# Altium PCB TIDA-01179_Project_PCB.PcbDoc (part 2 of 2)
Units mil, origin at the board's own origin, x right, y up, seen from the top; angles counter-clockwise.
Board outline 3149.61 x 2755.91 mil, 4 copper layers (Top Layer, 2nd Layer, 3rd layer, Bottom Layer), stack 51.6 mil thick; 141 components, 52 nets, 310 pads, 228 vias.
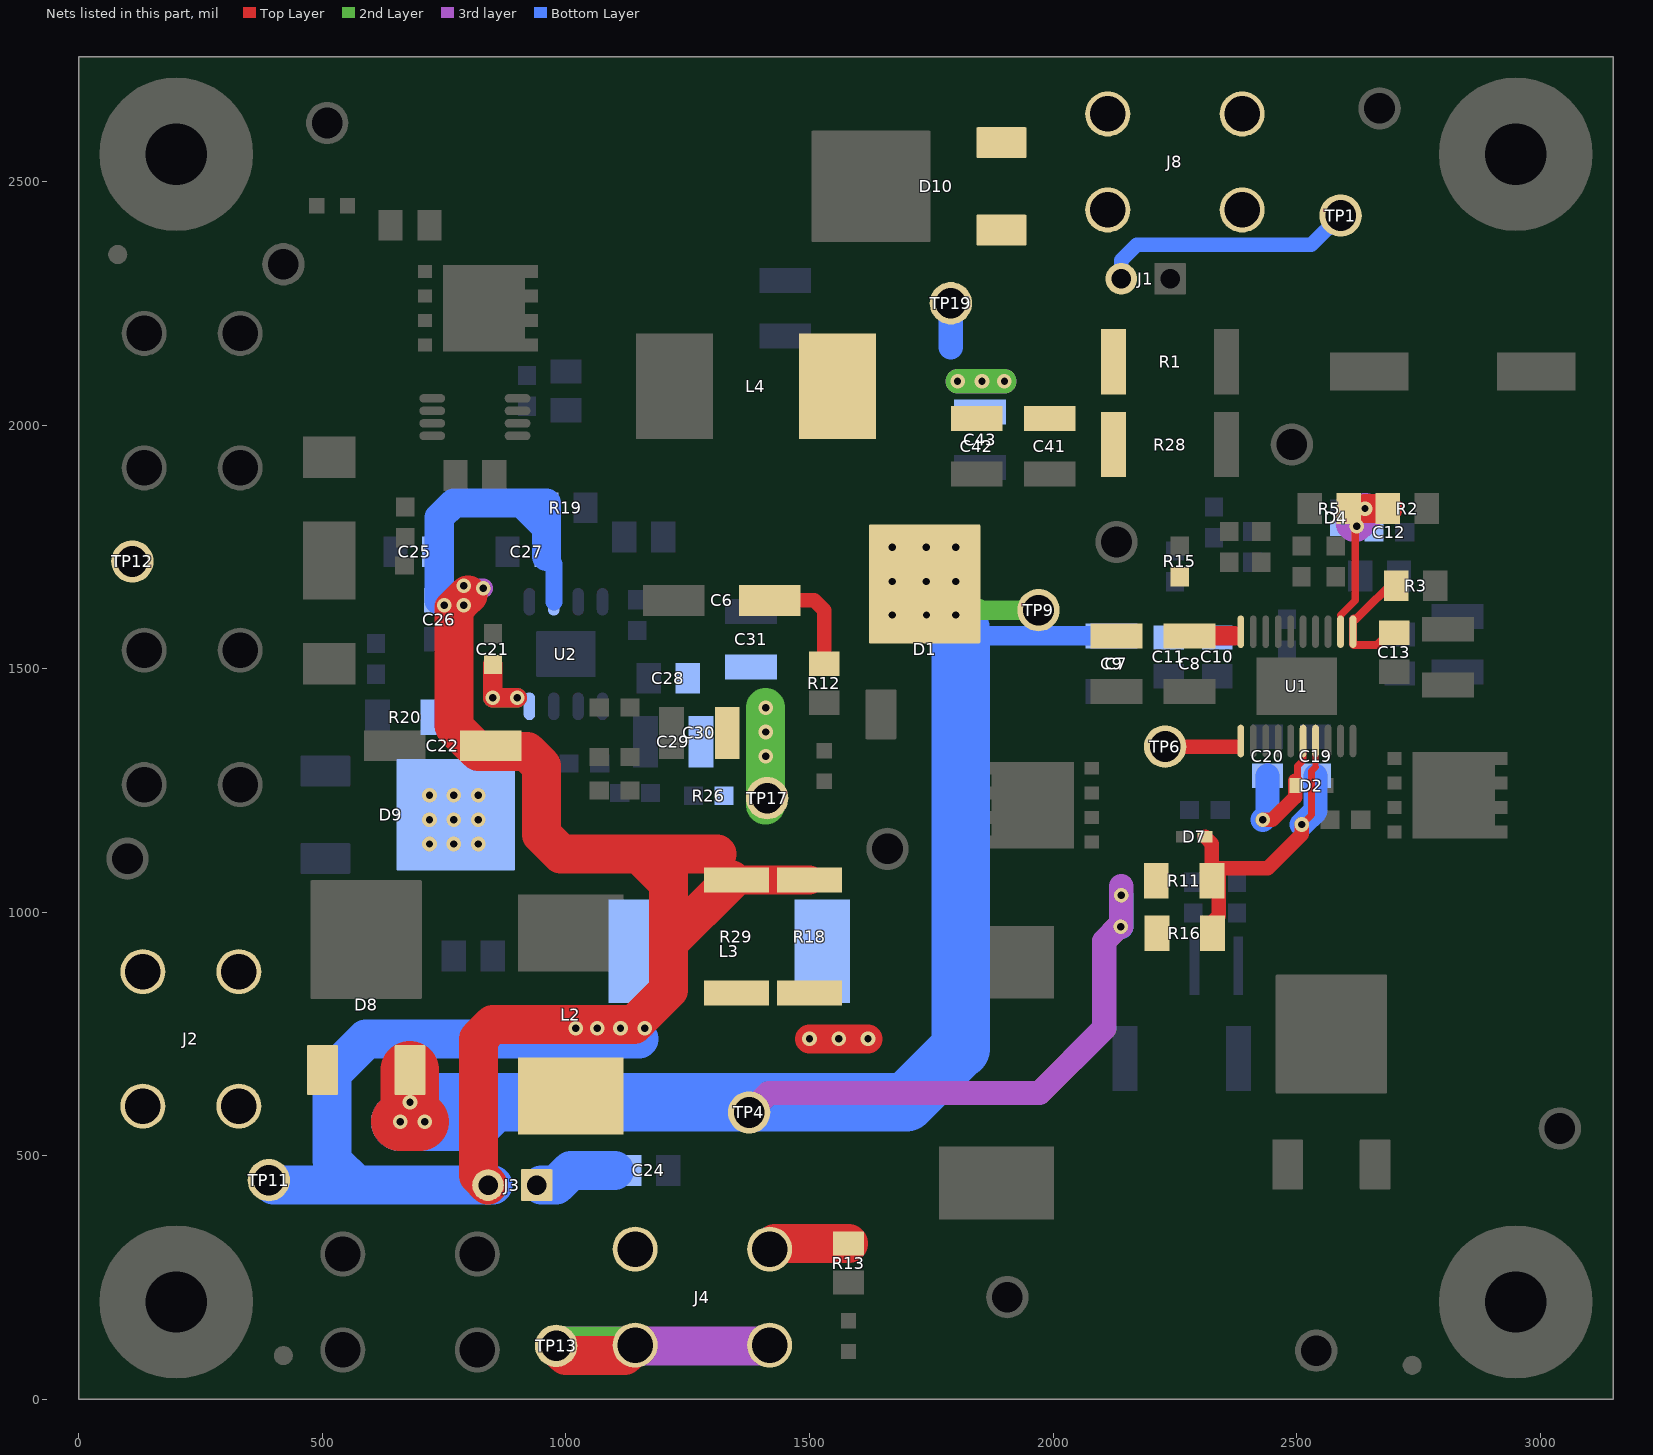
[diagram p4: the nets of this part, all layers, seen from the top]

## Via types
v1: diameter 30, hole 15, Top Layer to Bottom Layer, 210 vias
v2: diameter 19.68, hole 7.87, Top Layer to Bottom Layer, 12 vias
v3: diameter 19.68, hole 7.87, Top Layer to Bottom Layer, tented top, 6 vias

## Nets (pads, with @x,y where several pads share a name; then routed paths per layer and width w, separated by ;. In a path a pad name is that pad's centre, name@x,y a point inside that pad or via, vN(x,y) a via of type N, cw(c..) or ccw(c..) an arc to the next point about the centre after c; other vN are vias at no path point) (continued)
SW_540: C21.1 D9.4 L3.1 R20.2 TP12.1 U2.8 | length 168.5
  Top Layer w40: C21.1@850,1508.5 v1(850,1440) v1(900,1440)
  2nd Layer w40: v1(850,1440) v1(900,1440)
  other v1: 720,1140 770,1140 820,1140 720,1190 770,1190 820,1190 720,1240 770,1240 820,1240
SYNC_5118: TP6.1 U1.11 | length 147
  Top Layer w30: TP6.1@2230,1340 2377,1340
UVLO_5118: C12.1 D4.1 R2.1 R5.2 U1.2 | length 369.8
  Top Layer w13: U1.2@2589.8,1575.91 2589.8,1609.8
  Top Layer w15: 2589.8,1609.8 2620,1640 R5.2@2620,1800
  Top Layer w60: v1(2640,1828.54) R2.1@2686.61,1828.54
  3rd layer w80: v1@2620,1800 v1@2640,1820
  Bottom Layer w30: v1@2620,1800 v1@2640,1820 ; C12.1@2640,1798.5 v1@2640,1820 ; v1(2640,1828.54) v1@2640,1820
  other v1: 2623,1792
V_HVBAT_+12V: D10.1 D10.3 J8.1 J8.2 J8.3 J8.4
V_HVBAT_+15V: D8.1 J2.1 J2.2 J2.3 J2.4
VBAT_FILT: C41.1 C42.1 C43.1 J1.2 L4.2 R1.1 R28.1 TP1.1 TP19.1 | length 808.4
  3rd layer w50: v1(1803.86,2090) v1(1853.86,2090) v1(1900,2090)
  2nd Layer w50: v1(1803.86,2090) v1(1853.86,2090) v1(1900,2090)
  Bottom Layer w30: J1.2@2140,2300 2140,2338 2172,2370 2530,2370 TP1.1@2590,2430
  Bottom Layer w50: 1790,2160 TP19.1@1790,2250
VCC_5118: C20.1 D2.2 U1.16 | length 301.7
  Top Layer w13: 2513.03,1311.57 U1.16@2513.03,1351.5
  Top Layer w14: D2.2@2496.54,1270 2501.46,1274.92 2501.46,1300 2513.03,1311.57
  Top Layer w30: v1(2430,1190) 2450,1190 2496.54,1236.54 D2.2@2496.54,1270
  Bottom Layer w50: v1(2430,1190) 2440,1200 C20.1@2440,1280
VCCX_5118: C19.1 D7.1 R11.1 R16.1 U1.17 | length 739.6
  Top Layer w13: 2538.62,1298.31 U1.17@2538.62,1351.5
  Top Layer w14: v1(2510,1180) 2530,1200 2530,1289.68 2538.62,1298.31
  Top Layer w30: D7.1@2311.65,1154.57 2325.79,1140.43 R11.1@2325.79,1090 ; R11.1@2325.79,1064.57 R11.1@2325.79,1090 ; R16.1@2327.09,980 2340,992.91 R11.1@2340,1090 ; v1(2510,1180) 2510,1160 2440,1090 R11.1@2325.79,1090
  Bottom Layer w50: v1(2510,1180) 2538.62,1208.62 C19.1@2538.62,1280
VFILT_+15V: C24.1 J3.1 L2.2 R18.1 R29.1 | length 162.4
  Bottom Layer w80: J3.1@950,440 980,440 1010,470 1100,470
VIN_540: C22.1 C25.1 C26.1 C27.1 J3.2 R18.2 R19.2 R29.2 TP11.1 U2.2 | length 4816.6
  Top Layer w60: R29.2@1340,1066.14 R18.2@1500,1066.14
  Top Layer w80: 798.68,1651.62 770,1622.94 770,1383.16 772.07,1383.16 772.07,1377.93 820,1330 920,1330 950,1300 950,1160 990,1120 1150,1120 ; J3.2@840,440 820,460 820,740 850,770 1140,770 1210,840 1210,936.14 ; 1310,1120 1210,1120 ; R29.2@1340,1066.14 1210,936.14 ; 1150,1120 1210,1120 ; 1150,1120 1210,1060 ; 1210,936.14 1210,1060 ; 1210,1060 1210,1120
  3rd layer w40: v1@820,1660 v1(790,1630) v1(750,1630) 785.3,1665.3 v1(830,1665.3) ; v1(1020,762) v1(1064,762) v1(1112,762) v1(1162,762)
  Bottom Layer w35: U2.2@975,1637.28 C27.1@975,1715
  Bottom Layer w60: C26.1@740,1640 740,1810 770,1840 910,1840 ; C27.1@960,1730 960,1790 ; 910,1840 960,1840 960,1790 ; 910,1840 960,1790
  Bottom Layer w80: TP11.1@390,450 400,440 570,440 ; J3.2@850,440 J3.2@840,440 570,440 ; 1150,740 590,740 520,670 520,490 570,440
  other v1: 790,1670
VIN_5118: C13.1 R3.1 U1.1 | length 239.8
  Top Layer w17: R3.1@2690,1670 2640,1620 2622.48,1602.48 2616.92,1602.48 2615.39,1600.95 U1.1@2615.39,1575.91 2615.39,1550.14 2616.84,1548.69 2665.23,1548.69 C13.1@2690.24,1573.7
VOUT_+5V: C28.1 C29.1 C30.1 C31.1 J4.1 J4.2 J4.3 J4.4 L3.2 R13.2 R26.2 TP13.1 TP17.1 | length 1391.4
  Top Layer w60: v1(1500,740) v1(1560,740) v1(1620,740)
  Top Layer w80: TP13.1@980,110 1000,90 1120.5,90 J4.1@1142,111.5 ; J4.4@1418,308.5 1429.5,320 R13.2@1580,320
  3rd layer w40: v1(1500,740) v1(1560,740) v1(1620,740)
  3rd layer w80: TP13.1@980,110 1416.5,110 J4.3@1418,111.5 ; TP17.1@1410,1237 TP17.1@1413,1234
  2nd Layer w80: TP13.1@980,110 1140.5,110 J4.1@1142,111.5 ; TP17.1@1410,1220 v1(1410,1320) v1(1410,1370) v1(1410,1420)
VOUT_+15V: C6.1 C7.1 C8.1 C9.1 C10.1 C11.1 D1.4 D8.3 R11.2 R12.2 R15.2 R16.2 TP4.1 TP9.1 U1.10 | length 4381.8
  Top Layer w30: C6.1@1418.43,1640 1510,1640 1530,1620 R12.2@1530,1500
  Top Layer w40: C8.1@2280,1567.09 2372,1567.09
  Top Layer w120: v1(660,570) v1@700,570 ; 679.76,580.24 D8.3@679.76,676.14
  3rd layer w50: TP4.1@1376,589 1416,629 1972,629 2104.6,761.6 2104.6,940.92 2133.68,970 v1(2139,970) 2140,971 v1(2140,1034.57) 2140,1053
  2nd Layer w40: 1848,1623 1851,1620 TP9.1@1970,1620
  Bottom Layer w20: 1698,610 1718,590
  Bottom Layer w40: 1810,1567.09 C9.1@2120,1567.09
  Bottom Layer w50: v1@2140,970 v1(2140,1034.57)
  Bottom Layer w120: 1810,1580 1810,1567.09 1810,720 1808,720 1698,610 850,610 ; 850,610 700,610 v1(660,570) v1(710,570) 810,570 850,610
  other v1: 680,610 1670,1610 1740,1610 1800,1610 1670,1678.98 1739.61,1678.98 1800,1678.98 1670,1748.98 1739.61,1748.98 1800,1748.98
pads on no net: FID1.1 FID2.1 FID3.1 H1.1 H2.1 H3.1 H4.1 H5.0 H6.0 H7.0 H8.0

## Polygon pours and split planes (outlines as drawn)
GND on Top Layer "TOP_LAYER_GND_P298" (solid, remove dead copper, pour order 298): 0,0 3149.61,0 3149.61,2755.91 0,2755.91 0,0
VOUT_+5V on Top Layer "TOP_LAYER_VOUT_+5V_P270" (solid, remove dead copper, pour order 270): 1120,380 980,380 950,350 950,120 950,80 990,40 1490,40 1530,80 1530,332.48 1528.5,333.98 1528.5,341.5 1490,380 980,380
CATHODE on Top Layer "TOP_LAYER_CATHODE_P230" (solid, remove dead copper, pour order 230): 1430,1800 1430,2264.61 1750,2264.61 1750,2755.91 770,2755.91 765.91,2760 10,2760 0,2750 0,2120 20,2100 1060,2100 1100,2060 1100,1858.7 1158.7,1800
SW_540 on Top Layer "TOP_LAYER_SW_540_P248" (solid, remove dead copper, pour order 248): 660,1270 640,1250 640,1170 700.57,1109.43 702.35,1109.43 849.43,1109.43 880,1140 880,1250 860,1270
NetC23_1 on Top Layer "TOP_LAYER_NETC23_1_P251" (solid, remove dead copper, pour order 251): 490,1230 410,1150 410,830 489.06,750.94 490,750.94 500.94,740 1103.78,740 1160,796.22 1160,1120 1050,1230
V_HVBAT_+15V on Top Layer "TOP_LAYER_V_HVBAT_+15V_P250" (solid, remove dead copper, pour order 250): 0,950 80,1030 360,1030 430,960 430,940 430,760 460,730 470,730 550,730 560,720 560,710 560,580 490,510 100,510 50,510 0,560 0,950
SW1_5118 on Top Layer "TOP_LAYER_SW1_5118_P253" (solid, remove dead copper, pour order 253): 1782.45,1160 1782.45,702.45 1700,620 1700,248 1782,166 2156.3,166 2250,270.11 2250,530.86 2297,597 2699.74,597 2730,658.02 2730,1120 2690,1160
NetD3_1 on Top Layer "TOP_LAYER_NETD3_1_P247" (solid, remove dead copper, pour order 247): 2309.19,577.85 2679,577.85 2736,534.33 2736,273 2691,228 2298,228 2247.19,278.81 2247.19,500.35
GND on Top Layer "TOP_LAYER_GND_P244" (solid, remove dead copper, pour order 244): 2070,1260 2280,1260 2280,1133.07 2266.93,1120 2260,1120 2258.43,1121.57 2090,1121.57 2071.57,1140 2070,1140
SW2_5118 on Top Layer "TOP_LAYER_SW2_5118_P246" (solid, remove dead copper, pour order 246): 1630,1480 1940,1480 1960,1460 1960,1370 1970,1360 2020,1360 2040,1340 2040,1250 2040,760 1980,700 1650,700 1600,750 1600,1450 1630,1480 1631.97,1480
GND on Top Layer "TOP_LAYER_GND_P228" (solid, remove dead copper, pour order 228): 2446.85,1410 2006.85,1410 1986.85,1430 1986.85,1500 2006.85,1520 2326.85,1520 2446.85,1520
GND on Top Layer "TOP_LAYER_GND_P227" (solid, remove dead copper, pour order 227): 2420,1520 2860,1520 2880,1500 2880,1430 2860,1410 2540,1410 2420,1410
V_HVBAT_+12V on Top Layer "TOP_LAYER_V_HVBAT_+12V_P224" (solid, remove dead copper, pour order 224): 1840,2755.91 1840,2350 2500,2350 2500,2755.91
VBAT_FILT on Top Layer "TOP_LAYER_VBAT_FILT_P225" (solid, remove dead copper, pour order 225): 1624.99,2344.99 2180,2344.99 2180,1860 2160,1840 1500,1840 1450,1890 1450,2170
DC_LINK on Top Layer "TOP_LAYER_DC_LINK_P226" (solid, remove dead copper, pour order 226): 2250,2420 2220,2390 2220,2240 2220,1943.23 2283.23,1880 2740,1880 2810,1950 2810,2370 2760,2420 2750,2430 2250,2430
VIN_5118 on Top Layer "TOP_LAYER_VIN_5118_P220" (solid, remove dead copper, pour order 220): 2630,1730 2620,1720 2620,1540 2700,1540 2730,1540 2737.09,1540 2757.09,1560 2757.09,1712.91 2740,1730
GND on Top Layer "TOP_LAYER_GND_P223" (solid, remove dead copper, pour order 223): 2884.63,2250 3149.61,2250 3149.61,2020 2884.63,2020 2870,2034.63 2870,2040 2870,2235.37
DC_LINK on Top Layer "TOP_LAYER_DC_LINK_P232" (solid, remove dead copper, pour order 232): 2740,2430 3149.61,2430 3149.61,579.61 3060,490 2850,490 2740,600
VOUT_+15V on Top Layer "TOP_LAYER_VOUT_+15V_P229" (solid, remove dead copper, pour order 229): 2340,1490 2390,1540 2390,1751.65 2331.65,1810 1380,1810 1340,1770 1340,1550 1400,1490
SW1_5118 on Top Layer "TOP_LAYER_SW1_5118_P221" (solid, remove dead copper, pour order 221): 2620,1400 2730,1400 2730,1220 2710,1200 2630,1200 2620,1210
VFILT_+15V on Top Layer "TOP_LAYER_VFILT_+15V_P252" (solid, remove dead copper, pour order 252): 1576.77,930 1610,896.77 1610,440 1560,390 1520,390 990,390 930,390 860,460 860,670 900,710 1150,710 1220,780 1220,886.77 1263.23,930
VIN_540 on Top Layer "TOP_LAYER_VIN_540_P249" (solid, remove dead copper, pour order 249): 1260,1190 1230,1160 1230,1010 1270,970 1274.06,970 1284.06,960 1540,960 1570,990 1570,1160 1540,1190 1260,1190
GND on Top Layer "TOP_LAYER_GND_P222" (solid, remove dead copper, pour order 222): 2056.14,1960 1740,1960 1710,1930 1710,1850 1740,1820 2060,1820 2080,1840 2080,1940 2059.43,1960.57 1757.65,1960.57
VOUT_+5V on Top Layer "TOP_LAYER_VOUT_+5V_P245" (solid, remove dead copper, pour order 245): 1330,1490 1310,1490 1290,1470 1290,1257.2 1290,1240 1318.7,1211.3 1330,1211.3 1331.3,1210 1460,1210 1480,1230 1480,1240 1480,1460 1450,1490 1440,1490 1340,1490
SW2_5118 on 3rd layer "3RD_LAYER_SW2_5118_P302" (solid, remove dead copper, pour order 302): 1701,1480 1940,1480 1960,1460 1960,1370 1970,1360 2020,1360 2073,1307 2073,698 1930,555 1716,555 1644,627 1644,1423
GND on 3rd layer "3RD_LAYER_GND_P233" (solid, remove dead copper, pour order 233): 2799,1465 2799,1863 2637,2025 2279,2025 2219.74,1965.74 2219.74,1605.9 2156.84,1543 2008,1543 1968,1503 1968,1502 1968,1393 1968,1392 1992,1368 2015,1368 2128.43,1130 2591,1130 2646,1185 2646,1312
GND on 3rd layer "3RD_LAYER_GND_P231" (solid, remove dead copper, pour order 231): 954,1725 930,1701 930,1141 966,1105 1442,1105 1553,1216 1553,1536 1364,1725
CATHODE on 3rd layer "3RD_LAYER_CATHODE_P237" (solid, remove dead copper, pour order 237): 0,2750 0,2160 2220,2160 2220,2750 2094.09,2750
VOUT_+15V on 3rd layer "3RD_LAYER_VOUT_+15V_P235" (solid, remove dead copper, pour order 235): 960,2340 2210,2340 2210,1625 2153,1568 960,1568
DC_LINK on 3rd layer "3RD_LAYER_DC_LINK_P238" (solid, pour order 238): 3150,1160 2336,1160 2181,1315 2181,2750 3140,2750 3150,2760
SW1_5118 on 3rd layer "3RD_LAYER_SW1_5118_P239" (solid, remove dead copper, pour order 239): 2140,1160 3149.61,1160 3149.61,9.61 2080,9.61 2080,1100
NetC23_1 on 3rd layer "3RD_LAYER_NETC23_1_P236" (solid, remove dead copper, pour order 236): 0,1190 1127.48,1190 1127.48,7.48 1120,0 10,0 0,-10
SW_540 on 3rd layer "3RD_LAYER_SW_540_P234" (solid, remove dead copper, pour order 234): 690,1080 870,1080 900,1110 900,1200 950,1250 950,1420 950,2091.57 883.57,2158 68,2158 0,2090 0,1250 40,1210 630,1210 670,1170 670,1100
GND on Bottom Layer "BOTTOM_LAYER_GND_P300" (solid, remove dead copper, pour order 300): 0,0 3149.61,0 3149.61,2755.91 0,2755.91 0,0
V_HVBAT_+15V on Bottom Layer "BOTTOM_LAYER_V_HVBAT_+15V_P268" (solid, remove dead copper, pour order 268): 80,1030 360,1030 390,1000 390,570 363,543 333.5,543 70,543 0,613 0,960 70,1030
SW2_5118 on Bottom Layer "BOTTOM_LAYER_SW2_5118_P265" (solid, remove dead copper, pour order 265): 1893,1353 1754,1214 1754,383.01 1838,299 2064,299 2090.44,325.44 2089.98,1305.02 2042,1353
VIN_540 on Bottom Layer "BOTTOM_LAYER_VIN_540_P267" (solid, remove dead copper, pour order 267): 710,1890 710,1895.43 760,1945.43 974.57,1945.43 990,1930 990,1615.5 984.5,1610 730,1610 710,1610
ANODE on Bottom Layer "BOTTOM_LAYER_ANODE_P266" (solid, remove dead copper, pour order 266): 0,2200 100,2300 440,2300 520,2220 520,2210 520,1820 450,1750 100,1750 0,1850 0,1860 0,2200
NetD3_1 on Bottom Layer "BOTTOM_LAYER_NETD3_1_P243" (solid, remove dead copper, pour order 243): 2125.83,834 2266,834 2300,800 2300,629 2352,577 2352,377 2305,330 2127,330 2092,365 2092,793.4
DC_LINK on Bottom Layer "BOTTOM_LAYER_DC_LINK_P241" (solid, remove dead copper, pour order 241): 2691.46,1720 2680,1708.54 2680,1569.29 2699.29,1550 2700,1550 2757.09,1550 2776.85,1569.76 2873.23,1570 2880,1570 2890,1580 2890,1710 2880,1720
VOUT_+15V on Bottom Layer "BOTTOM_LAYER_VOUT_+15V_P242" (solid, remove dead copper, pour order 242): 2377.05,1540 1638.31,1540 1600,1578.31 1600,1770 1630,1800 2361.5,1800 2390,1771.5 2390,1552.95
SW_540 on Bottom Layer "BOTTOM_LAYER_SW_540_P255" (solid, remove dead copper, pour order 255): 746.77,1457.64 922.36,1457.64 930,1450 930,1170 970,1130 1180,1130 1220,1090 1220,830 1200,810 1040,810 990,860 970,880 970,980 940,1010 800,1010 730,1080 640,1080 630,1090 630,1289.92 700,1359.92 700,1436.26 721.38,1457.64 740,1457.64
NetC23_1 on Bottom Layer "BOTTOM_LAYER_NETC23_1_P254" (solid, remove dead copper, pour order 254): 460,1060 350,1060 310,1020 310,770 370,710 670,710 800,840 800,960 710,1050 700,1060 700,1060.87
VOUT_+5V on Bottom Layer "BOTTOM_LAYER_VOUT_+5V_P256" (solid, remove dead copper, pour order 256): 1690,710 1750,770 1750,780 1750,1400 1750,1510 1720,1540 1240,1540 1202.99,1502.99 1202.99,1287.01 1292.99,1287.01 1305,1275 1305,1115 1353.86,1066.14 1400,1066.14 1440,1026.14 1440,790 1440,750 1440,740 1470,710
VBAT_FILT on Bottom Layer "BOTTOM_LAYER_VBAT_FILT_P257" (solid, remove dead copper, pour order 257): 1710,2210 1670,2170 1670,2020 1700,1990 1740,1990 1940,1990 1990,1990 2030,2030 2030,2170 1990,2210
GND on Bottom Layer "BOTTOM_LAYER_GND_P240" (solid, remove dead copper, pour order 240): 1699.58,1950 1960,1950 2030,1950 2080,1900 2084.29,1895.71 2084.29,1832.2 2062.09,1810 2050,1810 1710,1810 1670,1850 1670,1920 1699.58,1949.58 1699.58,1950
CATHODE on Bottom Layer "BOTTOM_LAYER_CATHODE_P260" (solid, remove dead copper, pour order 260): 1106.11,2260 1730,2260 1810,2260 1880,2330 1880,2755.91 730,2755.91 665.91,2755.91 600,2690 600,2090 610,2080 1050,2080 1070,2100 1070,2214.86
SW1_5118 on Bottom Layer "BOTTOM_LAYER_SW1_5118_P259" (solid, remove dead copper, pour order 259): 2620,1060 2496,1060 2440,1004 2440,665 2521,584 2521,109 2630,0 3150,0 3150,609.61 3149.61,610 2878.84,610 2820,668.84 2820,960 2720,1060 2600,1060
DC_LINK on Bottom Layer "BOTTOM_LAYER_DC_LINK_P261" (solid, remove dead copper, pour order 261): 3060,1720 2810.14,1720 2660,1570.16 2660,1300 2660,1090 2680,1070 2700,1070 2730,1070 2800,1000 2800,980 2800,700 2800,650 2800,640 2840,600 3150,600 3150,1630
V_HVBAT_+12V on Bottom Layer "BOTTOM_LAYER_V_HVBAT_+12V_P258" (solid, remove dead copper, pour order 258): 1930,2710 1880,2660 1880,2405.2 1920,2365.2 1935.2,2350 2510,2350 2540,2380 2540,2400 2540,2710 2494.09,2755.91 2490,2755.91 1980,2755.91 1934.09,2710
GND on 2nd Layer "2ND_LAYER_GND_P304" (solid, remove dead copper, pour order 304): 0,0 3149.61,0 3149.61,2755.91 0,2755.91 0,0
SW1_5118 on 2nd Layer "2ND_LAYER_SW1_5118_P262" (solid, remove dead copper, pour order 262): 2449,962 2449,497 2508,438 2765,438 2832,505 2832,1015.29 2776.19,1070.42 2502.42,1070.42 2449,1017 2449,942
VOUT_+5V on 2nd Layer "2ND_LAYER_VOUT_+5V_P263" (solid, remove dead copper, pour order 263): 1440,780 1680,780 1700,760 1700,537 1563,400 1563,0 1010,0 1020,10 1020,330 1020,345.59 1144.41,470 1320,470 1330,480 1390,540 1390,770 1400,780 1410,780 1460,780

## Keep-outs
Keep-Out Layer:
  the board outline again, w10
  text ".Layer_Name" at 577,-858.49 h60

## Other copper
Top Layer:
  rectangle net VCCX_5118: 2300,920 2350,1050
  rectangle net VOUT_+15V: 2100,919.13 2240,1100
  pour cut-out: 2050,1110 2050.83,1110.83 2290,1110.83 2290,900 2289.71,900.29 2112.2,900.29 2111.9,900 2080,900 2050,870
  pour cut-out: 1030,2085 1030,2045 1070,2005 1070,1855 1023.31,1808.31 1023.31,1805 1002.92,1784.61 1170,1784.61 1170,1795 1110,1855 1110,2050 1075,2085
  pour cut-out: 1620,690 1620,440 1580,400 1630,350 1630,330 1623.67,323.67 1623.67,154.78 1628.46,150 1690,150 1690,680 1680,690
  region net ANODE: 540,2350 520,2330 520,2220 550,2190 720,2190 730,2200 730,2332.13 712.13,2350
  region net 74610_GATE: 710,2120 700,2120 690,2110 690,2030 700,2020 740,2020 750,2030 750,2110 740,2120
  region net ANODE: 97,2247 70,2220 60,2210 60,1810 90,1780 390,1780 490,1880 490,1958.5 570,2038.5 570,2350 240,2350 137,2247
  text ".Layer_Name" at 597,-858.49 h60
3rd layer:
  rectangle net VOUT_+15V: 630,545.04 734.96,630
  rectangle net GND: 2870,2189.43 3104.22,2250
  rectangle net GND: 2360.2,1373 2615,1536.96
  text ".Layer_Name" at 577,-858.49 h60
2nd Layer:
  rectangle net VIN_540: 721.65,1601.02 840,1690
  rectangle net DC_LINK: 2707,1086 3108,1395
  rectangle net SW2_5118: 1824,684 2067,1347
  rectangle net VOUT_+15V: 1620,1580 1891,1802
  rectangle net CATHODE: 1404,2383 1746,2712
  rectangle net CATHODE: 670,2160 972,2419
  rectangle net SW_540: 634,1070.87 916,1270
  rectangle net NetC23_1: 440,821 814,1050
  text ".Layer_Name" at 590,-860 h60
Bottom Layer:
  rectangle net UVLO_5118: 2566.61,1751.46 2680,1800
  rectangle net EN_540: 1020,1731.46 1150,1858.54
  rectangle net VOUT_+5V: 1030,40 1580,370
  text ".Layer_Name" at 577,-858.49 h60

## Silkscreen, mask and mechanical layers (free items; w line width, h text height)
Top Overlay:
  text "GND" at 2530,2710 h60 r270
  text "GND" at 350,2680 h60
  text "'.PRJ_Number'.PCB_Rev" at 788,2540 h108.27
  text "HV_BAT_+12V" at 2020,2360 h60 r90
  text "BAT_IN+" at 120,2290 h60
  text "VBAT_ / FLT" at 2470,2250 h60
  text "VBAT / _FLT" at 1880,2190 h60
  text "BAT_ / IN+" at 440,2140 h60
  text "COMP / _5118" at 2400,2040 h60
  text "SW_Buck" at 190,1760 h60
  text "Vfb-" at 1950,1740 h60
  text "Vfb+" at 1910,1490 h60
  text "Vfb-" at 1630,1220 h60
  text "SYNC_5118" at 2130,1220 h60
  text "Vfb+" at 1218,1146 h60
  text "BAT_IN-" at 190,1140 h60
  text "BAT_ / +15V" at 190,1000 h60
  text "HV_BAT_+15V" at 410,930 h55 r270
  text "Vout / _+15V" at 1281,684 h60
  text "SW1_ / 5118" at 2930,490 h60 r90
  text "Vout_+5V" at 1173,401 h60
  text "Vin_BUCK" at 50,380 h60
  text "Vout_ / +5V" at 910,220 h60
  text "GND" at 2490,210 h60
  text "SW2 / _5118" at 1982,155 h60
  text "GND" at 450,140 h60 r90
  text ".Layer_Name" at 577,-858.49 h60
Bottom Overlay:
  text "RSNS" at 2320,576 h60
  text ".Layer_Name" at 577,-858.49 h60
Top Paste:
  rectangle: 937,1468 1077,1635
  text ".Layer_Name" at 577,-858.49 h60
Bottom Paste:
  rectangle: 2392,1409 2605,1501
  text ".Layer_Name" at 577,-858.49 h60
Top Solder:
  rectangle: 937,1468 1077,1635
  text ".Layer_Name" at 577,-858.49 h60
  text ".Layer_Name" at 577,-858.49 h60
Bottom Solder:
  rectangle: 2393,1409 2606,1502
  text ".Layer_Name" at 577,-858.49 h60
Drill Guide:
  text ".Layer_Name" at 577,-858.49 h60
M1 Board Outline:
  the board outline again, w10
  text ".Layer_Name" at 577,-858.49 h60
M2 Board Dimensions:
  rectangle: 125,-400 500,-275
  rectangle: 0,-275 125,-150
  lines w7: 0,-275 1000,-275 ; 125,-400 125,-150 ; 250,-400 250,-150 ; 500,-400 500,-150 ; 750,-400 750,-150 ; 0,-400 0,-150 1000,-150 1000,-400 0,-400
  text ".Layer_Name" at 577,-858.49 h60
M3 3D STEP Top:
  text ".Layer_Name" at 577,-858.49 h60
M4 3D STEP Bottom:
  text ".Layer_Name" at 577,-858.49 h60
M5 Assembly Top:
  lines w10: -292,-930.17 6308,-930.17 ; -292,-726.83 6310,-726.83 ; -292,-523.5 -292,-1133.5 3713,-1133.5 6310,-1133.5 6310,-523.5 -291.5,-523.5 -291.5,-1133.5 1284,-1133.5 ; 2173,-1133.5 2173,-523.5 ; 3440,-726.83 3440,-523.5 ; 4280,-726.83 4280,-523.5 ; 4902,-1140 4902,-937.17
  text "COMPONENTS MARKED 'DNP' SHOULD NOT BE POPULATED." at 1153.5,-318.5 h60
  text "ASSEMBLY VARIANT:" at 1153,-434 h60
  text ".VariantName" at 2189,-434 h60
  text "PCB VIEWED FROM TOP SIDE" at -228.5,-655.67 h60
  text "BOARD #:" at 2248,-655.67 h60
  text ".PRJ_Number" at 2793.5,-655.67 h60
  text "REV:" at 3638,-655.67 h60
  text ".PCB_Rev" at 3929.5,-655.67 h60
  text "SVN REV:" at 4476,-655.67 h60
  text ".VersionControl_RevNumber" at 4982,-655.67 h60
  text "TID #:" at 2248,-859 h60
  text ".TID" at 2793.5,-859 h60
  text "PLOT NAME =" at -228.5,-1064.34 h60
  text ".plot_File_Name" at 577,-1064.34 h60
  text "GENERATED    :" at 2250,-1064.34 h60
  text ".Print_Date" at 3119.5,-1064.34 h60
  text ".Print_Time" at 3848.5,-1064.34 h60
  text "TEXAS INSTRUMENTS" at 5113,-1064.34 h60
M6 Assembly Bottom:
  lines w10: -292.5,-727.33 6309.5,-727.33 ; -290.5,-930.67 6309.5,-930.67 ; 1115.5,-1140.5 1115.5,-937.67 ; 1737.5,-727.33 1737.5,-524 ; 2577.5,-727.33 2577.5,-524 ; 3844.5,-1134 3844.5,-524 ; 4733.5,-1134 6309,-1134 6309,-524 -292.5,-524 -292.5,-1134 2304.5,-1134 6309.5,-1134 6309.5,-524
  text "COMPONENTS MARKED 'DNP' SHOULD NOT BE POPULATED." at 6102,-318 h60
  text ".VariantName" at 5058,-434 h60
  text "ASSEMBLY VARIANT:" at 6097,-434 h60
  text ".VersionControl_RevNumber" at 1035.5,-656.17 h60
  text "SVN REV:" at 1541.5,-656.17 h60
  text ".PCB_Rev" at 2088,-656.17 h60
  text "REV:" at 2379.5,-656.17 h60
  text ".PRJ_Number" at 3224,-656.17 h60
  text "BOARD #:" at 3769.5,-656.17 h60
  text "PCB VIEWED FROM BOTTOM SIDE" at 6246,-656.17 h60
  text ".TID" at 3224,-859.5 h60
  text "TID #:" at 3769.5,-859.5 h60
  text "TEXAS INSTRUMENTS" at 904.5,-1064.84 h60
  text ".Print_Time" at 2169,-1064.84 h60
  text ".Print_Date" at 2898,-1064.84 h60
  text "GENERATED    :" at 3767.5,-1064.84 h60
  text ".plot_File_Name" at 5440.5,-1064.84 h60
  text "PLOT NAME =" at 6246,-1064.84 h60
M9 Title Sheet:
  drawing of 57 lines, arcs and shapes, not listed
  text "1" at 739.84,8036.5 h70
  text "2" at 3235.5,8036.5 h70
  text "3" at 5724.84,8036.5 h70
  text "4" at 8231.51,8036.5 h70
  text "5" at 10730.5,8036.5 h70
  text "6" at 13235.5,8036.5 h70
  text "A" at -416.5,6893.5 h70
  text "A" at 14383.5,6893.5 h70
  text "B" at -416.5,4513.5 h70
  text "B" at 14383.5,4513.5 h70
  text "C" at -416.5,2138.5 h70
  text "C" at 14383.5,2138.5 h70
  text "PROJECT TITLE:" at 11343.5,277.5 h45
  text ".PRJ_Title" at 11393.5,144.17 h70
  text "DESIGNED FOR:" at 11343.5,-23.5 h45
  text ".PRJ_Customer" at 11393.5,-163.5 h70
  text "D" at -416.5,-231.5 h70
  text "D" at 14383.5,-231.5 h70
  text "FILE NAME:" at 11343.5,-323.5 h45
  text ".PCB_File_Name_No_Path" at 11393.5,-443.5 h70
  text "Texas Instruments (TI) and/or its licensors do not warrant the accuracy or completeness of this specification" at 6374,-605.34 h45
  text "ENGINEER:" at 11343.5,-613.5 h45
  text "LAYOUT BY:" at 12848.5,-613.5 h45
  text "or any information contained therein. TI and/or its licensors do not warrant that this design will meet" at 6329.01,-718 h45
  text ".PRJ_Engineer" at 11393.5,-768.49 h70
  text ".PCB_Layout" at 12899,-768.49 h70
  text "the specifications, will be suitable for your application or fit for any particular purpose, or will operate in" at 6329.01,-830.67 h45
  text ".Layer_Name" at 577,-858.49 h60
  text "ALTIUM DESIGNER VERSION:" at 12848.5,-923.5 h45
  text "an implementation. TI and/or its licensors do not warrant that the design is production worthy. You should" at 6329.01,-943.33 h45
  text "completely validate and test your design implementation to confirm the system functionality for your application." at 6374,-1056 h45
  text ".print_Scale" at 11393.5,-1056.83 h70
  text ".Application_BuildNumber" at 12899,-1056.83 h70
  text "1" at 739.84,-1263.5 h70
  text "2" at 3235.5,-1263.5 h70
  text "3" at 5724.84,-1263.5 h70
  text "4" at 8231.51,-1263.5 h70
  text "5" at 10730.5,-1263.5 h70
  text "6" at 13235.5,-1263.5 h70
M10 Fab Notes:
  drawing of 173 lines, arcs and shapes, not listed
  text "DESIGN INFORMATION" at 12378.02,6201 h60
  text "MIN. TRACK WIDTH:" at 11733.46,6021 h60
  text "8" at 12829.7,6021 h60
  text "MIL" at 12984.46,6021 h60
  text "MIN. CLEARANCE:" at 11733.46,5889 h60
  text "0.2" at 12769.7,5889 h60
  text "mm" at 12984.46,5889 h60
  text "MIN. VIA PAD SIZE:" at 11733.46,5757 h60
  text "24" at 12799.71,5757 h60
  text "MIL" at 12984.46,5757 h60
  text "0.05mm (2MIL)" at 12428.46,5615.29 h60
  text "MINIMUM ANNULAR RING" at 11404.23,5611 h60
  text "EXTERNAL" at 13136.46,5611 h60
  text "PER" at 11604.23,5493 h60
  text "IPC-D-275 CLASS 2 LEVEL C" at 11824.23,5493 h60
  text "MIL, HOLES" at 13312.46,5380.71 h60
  text "+/-" at 12920,5380 h60
  text "+/-" at 13774,5380 h60
  text "REGISTRATION TOLERANCES:" at 11404.23,5375 h60
  text "METAL" at 12604,5375 h60
  text "5" at 13180.2,5375 h60
  text "3" at 14013.2,5375 h60
  text "MIL" at 14129.46,5375 h60
  text "+/-" at 13774,5262 h60
  text "HOLE SIZE TOLERANCE (UNLESS OTHERWISE SPECIFIED):" at 11404.23,5257 h60
  text "3" at 14013.2,5257 h60
  text "MIL" at 14129.46,5257 h60
  text "MATERIAL:" at 11329.46,5047.54 h60
  text "FR-4 High Tg" at 12315.9,4907.21 h60
  text "FR-408" at 11750.46,4898.64 h60
  text "OTHER" at 13238.46,4898.64 h60
  text "X" at 12161,4895 h60
  text "62 MIL (1.6mm) +/-10%" at 12070.56,4735.92 h60
  text "THICKNESS:" at 11404.23,4731.64 h60
  text "X" at 11942.4,4731.64 h60
  text "OTHER" at 13355.46,4731.64 h60
  text "TOLERANCE:" at 11404.23,4573.64 h60
  text "X" at 12243.53,4573.64 h60
  text "ANSI IPC-6012 TYPE 3 CLASS 2" at 12430.48,4573.64 h60
  text "OTHER +/-" at 12430.46,4417.64 h60
  text "BOW & TWIST:" at 11404.23,4260.64 h60
  text "X" at 12243.53,4260.64 h60
  text "ANSI IPC-6012 TYPE 3 CLASS 2" at 12430.48,4260.64 h60
  text "OTHER +/-" at 12430.46,4102.13 h60
  text "DRILLING:" at 11329.46,3963.64 h60
  text "REFERENCE:" at 11404.23,3846.64 h60
  text "X" at 12052.46,3846.64 h60
  text "AS SHOWN" at 12239.46,3846.64 h60
  text "X" at 12953.46,3846.64 h60
  text "NC_DRILL FILES" at 13090.46,3846.64 h60
  text "PTH COPPER THICKNESS:" at 11404.23,3688.64 h60
  text "X" at 12534.46,3688.64 h60
  text "20-30 um" at 12671.46,3688.64 h60
  text "OTHER" at 13388.46,3688.64 h60
  text "BOARD FINISH:" at 11329.46,3529.64 h60
  text "SILKSCREEN:" at 11484.68,3411.64 h60
  text "X" at 12433.46,3411.64 h60
  text "TOP" at 12559.46,3411.64 h60
  text "X" at 12943.46,3411.64 h60
  text "BOTTOM" at 13070.46,3411.64 h60
  text "SILKSCREEN COLOR:" at 11484.68,3244.64 h60
  text "X" at 12432.42,3244.64 h60
  text "WHITE" at 12559.46,3244.64 h60
  text "OTHER" at 13070.46,3244.64 h60
  text "X" at 12563.42,3085.44 h60
  text "GREEN" at 12690.46,3085.44 h60
  text "OTHER" at 13308.46,3085.44 h60
  text "SOLDER RESIST COLOR:" at 11484.68,3074.64 h60
  text "X" at 12563.42,2915.44 h60
  text "MATTE" at 12690.46,2915.44 h60
  text "SEMI-GLOSS" at 13308,2914.8 h60
  text "IMMERSION GOLD (ENIG)" at 12390.46,2726.92 h60
  text "ENEPIG" at 13728,2723.64 h60
  text "SURFACE FINISH:" at 11329.46,2722.64 h60
  text "X" at 12203.51,2722.64 h60
  text "IMM. TIN/SILVER OR EQUIV" at 11659,2565.64 h60
  text "OTHER" at 13090.46,2565.64 h60
  text "ARRAY/PANEL:" at 11329.46,2386.64 h60
  text "CUT AND TRIM PER M1 BOARD OUTLINE" at 12390.46,2382.35 h60
  text "N.C. ROUTE" at 12390.46,2230.64 h60
  text "X" at 13069.46,2230.64 h60
  text "V. SCORE" at 13256.46,2230.64 h60
  text "CERTIFICATION:" at 11329.46,2093.64 h60
  text "MATERIALS AND WORKMANSHIP FOR ALL PCBS" at 12054.46,2093.64 h60
  text "TO MEET OR EXCEED THE REQUIREMENTS OF:" at 12054.46,1995.64 h60
  text "X" at 11680.96,1859.13 h60
  text "ANSI IPC-A-600F CLASS ->" at 11819.96,1859.13 h60
  text "X" at 13459.02,1859.13 h60
  text "2" at 13577.96,1859.14 h60
  text "1" at 13262.96,1857.64 h60
  text "3" at 13931.96,1857.64 h60
  text "X" at 12495.02,1699.64 h60
  text "RoHS" at 12631.96,1699.64 h60
  text "OTHER" at 13276.36,1699.64 h60
  text "PER ORDER" at 13673.42,1699.64 h60
  text "ALL BOARDS MUST MEET OR EXCEED UL94-V0 REQUIREMENTS." at 11357,1534 h60
  text "PCB MUST BEAR THE UL94V-0 UL REGISTERED MATERIAL ID NUMBER" at 11357,1414 h60
  text "ADDITIONAL REQUIREMENTS:" at 11329.46,1240.64 h60
  text "MICROSECTION:" at 11404.23,1125.64 h60
  text "YES" at 12309.96,1125.64 h60
  text "REQUIRED" at 13171.46,969.49 h60
  text "BARE BOARD ELEC. TEST:" at 11404.23,966.64 h60
  text "NONE" at 12709.96,966.64 h60
  text "X" at 13044.46,966.64 h60
  text "PER ORDER" at 13763.46,966.64 h60
  text ".Layer_Name" at 577,-858.49 h60
M11 Gerber Information:
  lines w10: -292,-930.17 6308,-930.17 ; -292,-726.83 6310,-726.83 ; -292,-523.5 -292,-1133.5 3713,-1133.5 6310,-1133.5 6310,-523.5 -291.5,-523.5 -291.5,-1133.5 1284,-1133.5 ; 2173,-1133.5 2173,-523.5 ; 3440,-726.83 3440,-523.5 ; 4280,-726.83 4280,-523.5 ; 4902,-1140 4902,-937.17
  text "ALL ARTWORK VIEWED FROM TOP SIDE" at -228.5,-655.67 h60
  text "BOARD #:" at 2248,-655.67 h60
  text ".PRJ_Number" at 2793.5,-655.67 h60
  text "REV:" at 3638,-655.67 h60
  text ".PCB_Rev" at 3929.5,-655.67 h60
  text "SVN REV:" at 4476,-655.67 h60
  text ".VersionControl_RevNumber" at 4982,-655.67 h60
  text "LAYER NAME =" at -228.5,-858.49 h60
  text "TID #:" at 2248,-859 h60
  text ".TID" at 2793.5,-859 h60
  text "PLOT NAME =" at -228.5,-1064.34 h60
  text ".plot_File_Name" at 577,-1064.34 h60
  text "GENERATED    :" at 2250,-1064.34 h60
  text ".Print_Date" at 3119.5,-1064.34 h60
  text ".Print_Time" at 3848.5,-1064.34 h60
  text "TEXAS INSTRUMENTS" at 5113,-1064.34 h60
M12 Stackup:
  drawing of 295 lines, arcs and shapes, not listed
  text "Layer" at 9451.5,7765.5 h60
  text "Name" at 9861.41,7765.5 h60
  text "Material" at 10791.16,7765.5 h60
  text "Thickness" at 11650.92,7765.5 h60
  text "Constant" at 12300.76,7765.5 h60
  text "Board Layer Stack" at 12870.62,7765.5 h60
  text "1" at 9451.5,7645.5 h60
  text "Top Overlay" at 9861.41,7645.5 h60
  text "2" at 9451.5,7525.5 h60
  text "Top Solder" at 9861.41,7525.5 h60
  text "Solder Resist" at 10791.16,7525.5 h60
  text "0.010mm" at 11650.92,7525.5 h60
  text "3.5" at 12300.76,7525.5 h60
  text "3" at 9451.5,7405.5 h60
  text "Top Layer" at 9861.41,7405.5 h60
  text "Copper" at 10791.16,7405.5 h60
  text "0.036mm" at 11650.92,7405.5 h60
  text "4" at 9451.5,7285.5 h60
  text "Dielectric1" at 9861.41,7285.5 h60
  text "FR-4" at 10791.16,7285.5 h60
  text "0.127mm" at 11650.92,7285.5 h60
  text "4.2" at 12300.76,7285.5 h60
  text "5" at 9451.5,7165.5 h60
  text "2nd Layer" at 9861.41,7165.5 h60
  text "Copper" at 10791.16,7165.5 h60
  text "0.036mm" at 11650.92,7165.5 h60
  text "6" at 9451.5,7045.5 h60
  text "Dielectric 2" at 9861.41,7045.5 h60
  text "FR-4" at 10791.16,7045.5 h60
  text "0.914mm" at 11650.92,7045.5 h60
  text "4.2" at 12300.76,7045.5 h60
  text "7" at 9451.5,6925.5 h60
  text "3rd layer" at 9861.41,6925.5 h60
  text "Copper" at 10791.16,6925.5 h60
  text "0.036mm" at 11650.92,6925.5 h60
  text "8" at 9451.5,6805.5 h60
  text "Dielectric 3" at 9861.41,6805.5 h60
  text "FR-4" at 10791.16,6805.5 h60
  text "0.127mm" at 11650.92,6805.5 h60
  text "4.2" at 12300.76,6805.5 h60
  text "9" at 9451.5,6685.5 h60
  text "Bottom Layer" at 9861.41,6685.5 h60
  text "Copper" at 10791.16,6685.5 h60
  text "0.036mm" at 11650.92,6685.5 h60
  text "10" at 9451.5,6565.5 h60
  text "Bottom Solder" at 9861.41,6565.5 h60
  text "Solder Resist" at 10791.16,6565.5 h60
  text "0.010mm" at 11650.92,6565.5 h60
  text "3.5" at 12300.76,6565.5 h60
  text "11" at 9451.5,6445.5 h60
  text "Bottom Overlay" at 9861.41,6445.5 h60
  text ".Layer_Name" at 577,-858.49 h60
M13 Component Bodies Top:
  text ".Layer_Name" at 577,-858.49 h60
M14 Component Bodies Bottom:
  text ".Layer_Name" at 577,-858.49 h60
M15 Courtyards Top:
  text ".Layer_Name" at 577,-858.49 h60
M16 Courtyards Bottom:
  text ".Layer_Name" at 577,-858.49 h60
Drill Drawing:
  circle w10: c4923.73,6334.58 r27.63
  lines w10: 4896.1,6431.29 4951.36,6431.29 4951.36,6486.55 4896.1,6486.55 4896.1,6431.29 ; 4896.1,6610.89 4951.36,6610.89 4923.73,6555.62 4896.1,6610.89 ; 4896.1,6693.78 4909.91,6693.78 4923.73,6679.96 4937.54,6693.78 4951.36,6693.78 4937.54,6707.59 4951.36,6721.41 4937.54,6721.41 4923.73,6735.22 4909.91,6721.41 4896.1,6721.41 4909.91,6707.59 4896.1,6693.78 ; 4896.1,6804.3 4896.1,6818.11 4909.91,6831.93 4896.1,6845.74 4896.1,6859.56 4909.91,6859.56 4923.73,6845.74 4937.54,6859.56 4951.36,6859.56 4951.36,6845.74 4937.54,6831.93 4951.36,6818.11 4951.36,6804.3 4937.54,6804.3 4923.73,6818.11 4909.91,6804.3 4896.1,6804.3 ; 4896.1,6928.63 4923.73,6942.45 4951.36,6928.63 4937.54,6956.26 4951.36,6983.89 4923.73,6970.08 4896.1,6983.89 4909.91,6956.26 4896.1,6928.63
  lines w12: 4846,6269.65 8076.06,6269.65 ; 4846,7015.66 8076.06,7015.66 ; 5183.75,6145.32 5183.75,7140 ; 5515.56,6145.32 5515.56,7140 ; 6151.66,6145.32 6151.66,7140 ; 6410.66,6145.32 6410.66,7140 ; 6785.64,6145.32 6785.64,7140 ; 7509.86,6145.32 7509.86,7140 ; 4846,6145.32 8076.06,6145.32 8076.06,7140 4846,7140 4846,6145.32
  text "Symbol" at 4920.6,7052.97 h72
  text "Quantity" at 5221.05,7052.97 h72
  text "Finished Hole Size" at 5552.86,7052.97 h72
  text "Plated" at 6188.96,7052.97 h72
  text "Hole Type" at 6447.96,7052.97 h72
  text "Drill Layer Pair" at 6822.94,7052.97 h72
  text "Hole Tolerance" at 7547.16,7052.97 h72
  text "18" at 5221.05,6928.63 h60
  text "0.200mm (7.87mil)" at 5552.86,6928.63 h60
  text "PTH" at 6188.96,6928.63 h60
  text "Round" at 6447.96,6928.63 h60
  text "Top Layer - Bottom Layer" at 6822.94,6928.63 h60
  text "210" at 5221.05,6804.3 h60
  text "0.381mm (15.00mil)" at 5552.86,6804.3 h60
  text "PTH" at 6188.96,6804.3 h60
  text "Round" at 6447.96,6804.3 h60
  text "Top Layer - Bottom Layer" at 6822.94,6804.3 h60
  text "4" at 5221.05,6679.96 h60
  text "1.016mm (40.00mil)" at 5552.86,6679.96 h60
  text "PTH" at 6188.96,6679.96 h60
  text "Round" at 6447.96,6679.96 h60
  text "Top Layer - Bottom Layer" at 6822.94,6679.96 h60
  text "19" at 5221.05,6555.62 h60
  text "1.600mm (63.00mil)" at 5552.86,6555.62 h60
  text "PTH" at 6188.96,6555.62 h60
  text "Round" at 6447.96,6555.62 h60
  text "Top Layer - Bottom Layer" at 6822.94,6555.62 h60
  text "24" at 5221.05,6431.29 h60
  text "1.850mm (72.83mil)" at 5552.86,6431.29 h60
  text "PTH" at 6188.96,6431.29 h60
  text "Round" at 6447.96,6431.29 h60
  text "Top Layer - Bottom Layer" at 6822.94,6431.29 h60
  text "4" at 5221.05,6306.95 h60
  text "3.200mm (125.98mil)" at 5552.86,6306.95 h60
  text "PTH" at 6188.96,6306.95 h60
  text "Round" at 6447.96,6306.95 h60
  text "Top Layer - Bottom Layer" at 6822.94,6306.95 h60
  text "279 Total" at 5221.05,6182.62 h60
  text ".Layer_Name" at 577,-858.49 h60
M17 Embedded Cavity:
  text ".Layer_Name" at 577,-858.49 h60
M18 Embedded Assembly:
  text ".Layer_Name" at 577,-858.49 h60
M19 Embedded Keepout:
  text ".Layer_Name" at 577,-858.49 h60

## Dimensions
0,0 to 3149.61,0 on M2 Board Dimensions
0,0 to 0,2755.91 on M2 Board Dimensions
0,-400 to 1000,-400 on M2 Board Dimensions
